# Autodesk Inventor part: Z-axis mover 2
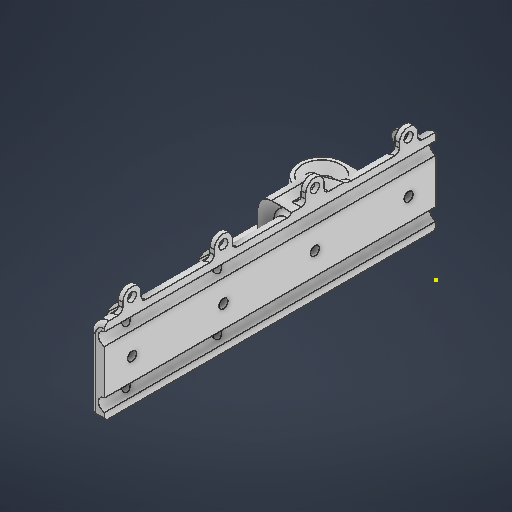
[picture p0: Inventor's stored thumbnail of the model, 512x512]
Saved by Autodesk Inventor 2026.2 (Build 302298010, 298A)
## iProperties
Created: 2026-04
Part Number: Z-axis mover 2
Material: 일반
Document SubType Name: Modeling
Designer: work
Density: 1 g/cm^3
Appearance: 기본값
Author: work
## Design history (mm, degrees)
sketch "스케치1"
  geometry: L1 (0, 0)-(8, 0); L2 (0, 0)-(0, 8); L3 (0, 0)-(-8, 0); L4 (0, 0)-(0, -8); L5 (0, 0)-(50, 0); L6 (0, 0)-(-50, 0); L7 (0, 0)-(0, 50); L8 (25, 0)-(25, -380); L9 (-25, 0)-(-25, -380); L10 (-25, 0)-(-25, 70); L11 (25, -380)-(-25, -380); L12 (25, 0)-(25, 0); L13 (25, 0)-(25, 120); L14 (-37.5, -395)-(37.5, -395); L15 (37.5, -395)-(37.5, -365); L16 (37.5, -365)-(-37.5, -365); L17 (-37.5, -365)-(-37.5, -395); L18 (-37.5, -395)-(37.5, -365); L19 (37.5, -395)-(-37.5, -365); L20 (-62.5, 38)-(62.5, 38); L21 (62.5, 38)-(62.5, -38); L22 (62.5, -38)-(-62.5, -38); L23 (-62.5, -38)-(-62.5, 38); L24 (-62.5, 38)-(62.5, -38); L25 (62.5, 38)-(-62.5, -38); L26 (62.5, -25)-(-62.5, -25); L27 (17, 38)-(-17, 38); L28 (-17, 38)-(-17, 61); L29 (-17, 61)-(17, 61); L30 (17, 61)-(17, 38); L31 (-22, 60.236)-(-22, 100); L32 (-22, 100)-(-28, 100); L33 (-28, 100)-(-28, -380); L34 (-28, -380)-(-22, -380); L35 (-22, -380)-(-22, 100); L36 (-40, 38)-(40, 38); L37 (40, 38)-(40, 18); L38 (40, 18)-(-40, 18); L39 (-40, 18)-(-40, 38); C1 r 5.25 at (0, 0); C2 r 11.3 at (0, 0); C3 r 2 at (8, 0); C4 r 2 at (0, 8); C5 r 2 at (-8, 0); C6 r 2 at (0, -8); C7 r 4.4 at (50, 0); C8 r 4.4 at (-50, 0); C9 r 4 at (0, 50); 7 further points
  constraints: 78 end point, 12 midpoint, 10 parallel, 9 centre point, 9 coincident, 8 horizontal, 6 perpendicular, 6 point on line, 5 vertical, 2 symmetric about line, 1 collinear, 22 other
  dimensions: "d0" = 10.5 diameter of C1; "d1" = 22.6 diameter of C2; "d2" = 8 distance of L1.start L1.end; "d3" = 4 diameter of C3; "d6" = 360 deg dimension on C1.centre L1.end (derived); "d8" = 50 distance of L4.start L5.end; "d9" = 8.8 diameter of C7; "d10" = 50 distance of L4.start L7.end; "d11" = 8 diameter of C9; "d12" = 12 distance of point (0, 38) L7.end; "d15" = 450 distance of L9.end L10.end; "d16" = 25 distance from line of point (0, 0) L8; "d17" = 25 distance from line of L10 C1.centre; "d19" = 500 distance of L8.end L13.end; "d20" = 120 vertical distance of point (0, 0) L13.end; "d21" = 75 distance between parallel lines of L17 L15; "d22" = 30 distance of L14.end L15.end; "d23" = 125 distance between parallel lines of L23 L21; "d24" = 25 distance from line of point (0, 0) L26; "d25" = 340 distance between parallel lines of L16 L26 (derived); "d26" = 34 distance of L28.end L29.end; "d27" = 23 distance of L27.end L28.end; "d30" = 6 distance between parallel lines of L33 L35; "d31" = 80 distance of L37.end L38.end; "d32" = 20 distance of L36.end L37.end; "d60" = 30 distance of L10.end point (-25, 100)
  node "스케치 - 원형 패턴1" dims "d6" = 360 deg (derived)
extrude "돌출1" new body sketch "스케치1" distance "d33" = 6; taper "d34" = 0 deg
extrude "돌출2" join sketch "스케치1" distance "d35" = 4; taper "d36" = 0 deg
extrude "돌출3" join sketch "스케치1" distance "d37" = 38; taper "d38" = 0 deg
sketch "스케치2"
  geometry: L1 (102.5, 6)-(22.5, 6) reference; L2 (87.5, 6)-(87.5, 31); L3 (93.5, 6)-(93.5, 31); L4 (81.5, 31)-(81.5, 6); L5 (0, 0)-(125, 0) reference; L6 (62.5, 6)-(37.5, 6); L7 (37.5, 6)-(37.5, 31); L8 (37.5, 31)-(62.5, 31); L9 (62.5, 31)-(62.5, 6); L10 (30.5, 4)-(44.5, 4); L11 (44.5, 4)-(44.5, 18); L12 (44.5, 18)-(30.5, 18); L13 (30.5, 18)-(30.5, 4); L14 (30.5, 4)-(44.5, 18); L15 (44.5, 4)-(30.5, 18); L16 (44.5, -10.5)-(86.5, -10.5); L17 (86.5, -10.5)-(86.5, 32.5); L18 (86.5, 32.5)-(44.5, 32.5); L19 (44.5, 32.5)-(44.5, -10.5); L20 (44.5, -10.5)-(86.5, 32.5); L21 (86.5, -10.5)-(44.5, 32.5); L22 (47.5, 32.5)-(47.5, -10.5); L23 (37.5, 6)-(37.5, 31); L24 (43.5, 6)-(43.5, 31); L25 (31.5, 31)-(31.5, 6); L26 (47, 1.5)-(28, 1.5); L27 (28, 1.5)-(28, 20.5); L28 (28, 20.5)-(47, 20.5); L29 (47, 20.5)-(47, 1.5); L30 (47, 1.5)-(28, 20.5); L31 (28, 1.5)-(47, 20.5); C1 r 2.75 at (87.5, 6); C2 r 2.75 at (87.5, 31); C3 r 4.25 at (37.5, 31); A1 r 6 centre (87.5, 6) between (81.5, 6) and (93.5, 6); A2 r 6 centre (87.5, 31) between (93.5, 31) and (81.5, 31); A3 r 6 centre (37.5, 6) between (31.5, 6) and (43.5, 6); A4 r 6 centre (37.5, 31) between (43.5, 31) and (31.5, 31); 16 further points
  constraints: 62 end point, 11 midpoint, 10 parallel, 10 tangent, 8 point on circle, 7 centre point, 7 perpendicular, 5 point on line, 4 horizontal, 2 coincident
  dimensions: "d39" = 5.5 diameter of C1; "d40" = 25 distance of L2.start L6.start; "d41" = 25 distance of L2.start L2.end; "d42" = 5.5 diameter of C2; "d43" = 25 distance of L7.end L8.end; "d44" = 25 distance of L6.end L7.end; "d45" = 8.5 diameter of C3; "d46" = 14 distance of L11.end L12.end; "d47" = 14 distance of L10.end L11.end; "d48" = 43 distance of L16.end L17.end; "d50" = 20 distance of L7.end point (37.5, 11); "d51" = 39 distance between parallel lines of L17 L22; "d52" = 3 distance between parallel lines of L22 L19; "d59" = 2.5 distance between parallel lines of L28 L12
extrude "돌출4" join sketch "스케치2" distance "d53" = 145; taper "d54" = 0 deg
extrude "돌출5" cut sketch "스케치2" extent not by distance; stored distance "d55" = 10; taper "d56" = 0 deg
sketch "스케치3"
  geometry: L1 (-31.5, 20.5)-(-31.5, 31) reference; L2 (-43.5, 31)-(-43.5, 20.5) reference; L3 (-30.5, 4)-(-44.5, 4) reference; L4 (-44.5, 18)-(-30.5, 18) reference; L5 (-28, 20.5)-(-31.5, 20.5) reference; L6 (-43.5, 20.5)-(-47, 20.5) reference; L7 (-47, 1.5)-(-41.469, 1.5) reference; L8 (-33.531, 1.5)-(-28, 1.5) reference; L9 (-28, 1.5)-(-28, 20.5) reference; L10 (-30.5, 18)-(-30.5, 4) reference; L11 (-44.5, 4)-(-44.5, 18) reference; L12 (-47, 20.5)-(-47, 1.5) reference; C1 r 6 at (-37.5, 31); A1 r 6 centre (-37.5, 6) between (-41.469, 1.5) and (-33.531, 1.5) reference; A2 r 6 centre (-37.5, 31) between (-31.5, 31) and (-43.5, 31) reference; 5 further points
  constraints: 1 centre point, 1 concentric
extrude "돌출6" cut sketch "스케치3" stored distance "d57" = 145; taper "d58" = 0 deg
sketch "스케치5"
  geometry: L1 (29.25, 38)-(20.75, 38) reference; L2 (18, 38)-(32, 38) reference; L3 (32, 38)-(18, 38) reference; L4 (-25, 38)-(62.5, 38) reference; L5 (40, 38)-(62.5, 38) reference; L6 (-40, 38)-(40, 38) reference; L7 (-62.5, 38)-(-40, 38) reference; L8 (-62.5, 38)-(-25, 38) reference; L9 (-25, 38)-(-31, 38) reference; L10 (-31, 38)-(-19, 38) reference; L11 (-19, 38)-(-25, 38) reference; L12 (25, 38)-(25, 88); L13 (9.5, 103.5)-(40.5, 103.5); L14 (40.5, 103.5)-(40.5, 72.5); L15 (40.5, 72.5)-(9.5, 72.5); L16 (9.5, 72.5)-(9.5, 103.5); L17 (9.5, 103.5)-(40.5, 72.5); L18 (40.5, 103.5)-(9.5, 72.5); L19 (1.5, 111.5)-(48.5, 111.5); L20 (48.5, 111.5)-(48.5, 64.5); L21 (48.5, 64.5)-(1.5, 64.5); L22 (1.5, 64.5)-(1.5, 111.5); L23 (1.5, 111.5)-(48.5, 64.5); L24 (48.5, 111.5)-(1.5, 64.5); L25 (-22.25, 120)-(-22.25, -25) reference; L26 (-31, 38)-(-19, 38) reference; L27 (-31, 38)-(-31, 120) reference; L28 (-19, 120)-(-31, 120) reference; L29 (-19, 38)-(-19, 120) reference; L30 (62.5, 38)-(62.5, -25) reference; L31 (40, 18)-(40, 38) reference; L32 (-62.5, 38)-(-25, 38) reference; L33 (-62.5, -25)-(-62.5, 38) reference; L34 (62.5, -25)-(-62.5, -25) reference; L35 (62.5, 38)-(62.5, -25) reference; L36 (-25, 38)-(62.5, 38) reference; L37 (-19, 38)-(19, 38); L38 (19, 38)-(19, 62); L39 (19, 62)-(-19, 62); L40 (-19, 62)-(-19, 38); L41 (-19, 38)-(-19, 120) reference; C1 r 12.5 at (25, 88); C2 r 2 at (9.5, 72.5); C3 r 2 at (40.5, 103.5); C4 r 2 at (9.5, 103.5); C5 r 2 at (40.5, 72.5); C6 r 2 at (0, -8) reference; C7 r 2 at (8, 0) reference; C8 r 2 at (0, 8) reference; C9 r 2 at (-8, 0) reference; C10 r 5.25 at (0, 0) reference; C11 r 4.4 at (50, 0) reference; C12 r 4.4 at (-50, 0) reference; A1 r 28.971 centre (1.5, 140.471) between (-19, 120) and (1.5, 111.5); A2 r 15 centre (63.5, 64.5) between (48.5, 64.5) and (55.046, 52.109); A3 r 17.08 centre (45.42, 38) between (62.5, 38) and (55.046, 52.109); 15 further points
  constraints: 34 end point, 8 centre point, 6 parallel, 6 point on circle, 5 coincident, 5 midpoint, 4 perpendicular, 4 tangent, 3 horizontal, 2 point on line, 5 other
  dimensions: "d61" = 25 distance from line of point (0, 38) L12; "d62" = 25 diameter of C1; "d63" = 31 distance of L14.end L15.end; "d64" = 31 distance of L13.end L14.end; "d65" = 4 diameter of C2; "d66" = 4 diameter of C3; "d67" = 4 diameter of C4; "d68" = 4 diameter of C5; "d69" = 50 distance of L12.start L12.end; "d70" = 8 distance between parallel lines of L14 L20; "d71" = 15 radius of A2; "d73" = 24 distance of L39.end L37.start
extrude "돌출7" join sketch "스케치5" distance "d74" = 6; taper "d75" = 0 deg
sketch "스케치6"
  geometry: L1 (-81.5, 31)-(-81.5, 0) reference; L2 (-81.5, 0)-(-43.5, 0) reference; L3 (-43.5, 0)-(-43.5, 4) reference; L4 (-30.5, 6)-(-22.5, 6) reference; L5 (-44.5, 18)-(-44.5, 4) reference; L6 (-30.5, 18)-(-44.5, 18) reference; L7 (-30.5, 6)-(-30.5, 18) reference; L8 (-22.5, 6)-(-22.5, 38) reference; L9 (-102.5, 38)-(-22.5, 38) reference; L10 (-102.5, 6)-(-102.5, 38) reference; L11 (-125, 6)-(-102.5, 6) reference; L12 (-125, 0)-(-125, 6) reference; L13 (-125, 0)-(-93.5, 0) reference; L14 (-93.5, 0)-(-93.5, 31) reference; L15 (-81.5, 6)-(-81.5, 31) reference; L16 (-93.5, 31)-(-93.5, 0) reference; L17 (0, 0)-(-125, 0) reference; L18 (-93.5, 6)-(-81.5, 6); L19 (-81.5, 6)-(-81.5, 0); L20 (-81.5, 0)-(-93.5, 0); L21 (-93.5, 0)-(-93.5, 6); L22 (-81.5, 0)-(-93.5, 0) reference; L23 (-81.5, 0)-(-81.5, 6) reference; L24 (-90.25, 6)-(-84.75, 6) reference; L25 (-44.5, 4)-(-43.5, 4) reference; C1 r 4.25 at (-37.5, 31) reference; C2 r 2.75 at (-87.5, 31) reference; A1 r 6 centre (-87.5, 31) between (-81.5, 31) and (-93.5, 31) reference; A2 r 6 centre (-87.5, 31) between (-81.5, 31) and (-93.5, 31) reference; A3 r 2.75 centre (-87.5, 6) between (-84.75, 6) and (-90.25, 6) reference; 10 further points
  constraints: 8 end point, 2 parallel, 2 point on line, 1 horizontal, 1 perpendicular
extrude "돌출8" join sketch "스케치6" stored distance "d76" = 6; taper "d77" = 0 deg
sketch "스케치7"
  geometry: L1 (47, 6)-(81.5, 6) reference; L2 (47, 20.5)-(43.5, 20.5) reference; L3 (43.5, 20.5)-(43.5, 31) reference; L4 (31.5, 31)-(31.5, 20.5) reference; L5 (31.5, 20.5)-(28, 20.5) reference; L6 (28, 20.5)-(28, 6) reference; L7 (0, 6)-(28, 6) reference; L8 (0, 0)-(0, 6) reference; L9 (0, 0)-(125, 0) reference; L10 (125, 0)-(125, 6) reference; L11 (93.5, 6)-(125, 6) reference; L12 (93.5, 6)-(93.5, 31) reference; L13 (81.5, 31)-(81.5, 6) reference; L14 (44.5, 18)-(44.5, 4) reference; L15 (44.5, 4)-(30.5, 4) reference; L16 (30.5, 4)-(30.5, 18) reference; L17 (30.5, 18)-(44.5, 18) reference; L18 (43.5, 4)-(30.5, 4) reference; L19 (43.5, 4)-(43.5, 6) reference; L20 (30.5, 6)-(43.5, 6) reference; L21 (30.5, 4)-(30.5, 6) reference; L22 (81.5, 0)-(43.5, 0) reference; L23 (81.5, 0)-(81.5, 6) reference; L24 (43.5, 6)-(81.5, 6) reference; L25 (43.5, 0)-(43.5, 6) reference; L26 (47, 6)-(47, 20.5) reference; C1 r 2.75 at (87.5, 31) reference; C2 r 2.75 at (87.5, 6) reference; C3 r 2.75 at (87.5, 31) reference; A1 r 6 centre (37.5, 31) between (43.5, 31) and (31.5, 31) reference; A2 r 6 centre (87.5, 31) between (93.5, 31) and (81.5, 31) reference; 4 further points
extrude "돌출9" cut sketch "스케치7" extent not by distance; stored distance "d78" = 0; taper "d79" = 0 deg
sketch "스케치8"
  geometry: L1 (50.5, 10)-(74.5, 10); L2 (74.5, 10)-(74.5, 28); L3 (74.5, 28)-(50.5, 28); L4 (50.5, 28)-(50.5, 10); L5 (50.5, 10)-(74.5, 28); L6 (74.5, 10)-(50.5, 28); L7 (102.5, 38)-(22.5, 38) reference; L8 (62.5, 38)-(62.5, 0); C1 r 2 at (50.5, 28); C2 r 2 at (50.5, 10); C3 r 2 at (74.5, 10); C4 r 2 at (74.5, 28); 1 further point
  constraints: 14 end point, 4 centre point, 4 coincident, 4 midpoint, 2 parallel, 1 horizontal, 1 perpendicular, 1 vertical
  dimensions: "d80" = 24 distance of L3.end L2.end; "d81" = 18 distance of L2.end L1.end; "d82" = 4 diameter of C1; "d83" = 4 diameter of C2; "d84" = 4 diameter of C3; "d85" = 4 diameter of C4
extrude "돌출10" cut sketch "스케치8" extent not by distance; stored distance "d86" = 18 (derived); taper "d87" = 0 deg
sketch "스케치9"
  geometry: L1 (59, -32)-(59, -7) reference; L2 (71, -7)-(71, -32) reference; L3 (80, -32)-(71, -32) reference; L4 (80, -32)-(80, 0) reference; L5 (0, 0)-(80, 0) reference; L6 (0, -32)-(0, 0) reference; L7 (5.5, -32)-(0, -32) reference; L8 (5.5, -32)-(5.5, -17.5) reference; L9 (5.5, -17.5)-(9, -17.5) reference; L10 (9, -17.5)-(9, -7) reference; L11 (21, -7)-(21, -17.5) reference; L12 (21, -17.5)-(24.5, -17.5) reference; L13 (59, -32)-(24.5, -32) reference; L14 (24.5, -17.5)-(24.5, -32) reference; C1 r 2 at (28, -28) reference; C2 r 2 at (52, -28) reference; C3 r 2 at (28, -10) reference; C4 r 2 at (52, -10) reference; C5 r 2 at (52, -28) reference; A1 r 6 centre (65, -7) between (71, -7) and (59, -7) reference; A2 r 6 centre (15, -7) between (21, -7) and (9, -7) reference; 5 further points
  constraints: 4 coincident
hole "구멍1" sketch "스케치9" at (52, -10), (28, -10), (28, -28), (52, -28) diameter "d88" = 4; stored, may be unused: countersink angle "d92" = 90 deg, drill point angle "d94" = 0 deg; dims "d89" = 6, "d90" = 6.2, "d91" = 4, "d93" = 8
sketch "스케치10"
  geometry: L1 (32, -98.356)-(32, -111.5) reference; L2 (32, -111.5)-(48.5, -111.5) reference; L3 (48.5, -111.5)-(48.5, -64.5) reference; L4 (62.5, -38)-(62.5, 25) reference; L5 (62.5, 25)-(34.5, 25) reference; L6 (34.5, 25)-(34.5, -18) reference; L7 (34.5, -18)-(40, -18) reference; L8 (40, -18)-(40, -38) reference; L9 (32, -38)-(40, -38) reference; L10 (32, -38)-(32, -77.644) reference; L11 (-31, -18)-(-31, 25) reference; L12 (-31, 25)-(-62.5, 25) reference; L13 (-62.5, 25)-(-62.5, -38) reference; L14 (-62.5, -38)-(-40, -38) reference; L15 (-40, -38)-(-40, -18) reference; L16 (-40, -18)-(-31, -18) reference; L17 (-50, -10)-(-31, -10); L18 (-50, 10)-(-31, 10); L19 (50, 10)-(34.5, 10); L20 (50, -10)-(34.5, -10); C1 r 4.4 at (50, 0) reference; C2 r 2 at (40.5, -72.5) reference; C3 r 2 at (40.5, -103.5) reference; C4 r 4.4 at (-50, 0) reference; A1 r 15 centre (63.5, -64.5) between (55.046, -52.109) and (48.5, -64.5) reference; A2 r 17.08 centre (45.42, -38) between (55.046, -52.109) and (62.5, -38) reference; A3 r 12.5 centre (25, -88) between (32, -98.356) and (32, -77.644) reference; A4 r 10 centre (-50, 0) between (-50, -10) and (-50, 10); A5 r 10 centre (50, 0) between (50, 10) and (50, -10); 1 further point
  constraints: 8 end point, 4 perpendicular, 4 point on circle, 4 point on line, 4 tangent, 2 centre point, 2 coincident
  dimensions: "d95" = 20 diameter of A4; "d96" = 20 diameter of A5
extrude "돌출11" join sketch "스케치10" stored distance "d97" = 10; taper "d98" = 0 deg
fillet "모깎기1" dims "d99" = 6
sketch "스케치11"
  geometry: C1 r 4.25 at (0, 0) reference; 1 further point
extrude "돌출12" cut sketch "스케치11" extent not by distance; stored distance "d100" = 0; taper "d101" = 0 deg
fillet "모깎기2" dims "d102" = 2
fillet "모깎기3" dims "d103" = 0.5
chamfer "모따기1" distance "d104" = 1; stored, may be unused: second distance "d105" = 2, angle "d106" = 45 deg
sketch "스케치12"
  geometry: L1 (17.5, -61.936)-(17.5, -78) reference; L2 (17, -62)-(-17, -62) reference; L3 (-19, -60)-(-19, -118) reference; L4 (-21, -120)-(-19.813, -120) reference; L5 (1.5, -111.5)-(17.5, -111.5) reference; L6 (17.5, -98)-(17.5, -111.5) reference; L7 (42, -40)-(42, -17.621) reference; L8 (32.5, -78)-(32.5, -40) reference; L9 (32.5, -111.5)-(32.5, -98) reference; L10 (32.5, -111.5)-(42.5, -111.5) reference; L11 (48.5, -105.5)-(48.5, -64.5) reference; L12 (62.5, -38)-(62.5, 19) reference; L13 (56.5, 25)-(36.5, 25) reference; L14 (36.5, 16)-(36.5, 25) reference; L15 (50, 12)-(40.5, 12) reference; L16 (45.657, -12)-(50, -12) reference; L17 (42, -40)-(42, -17.621) reference; L18 (32.5, -40)-(42, -40) reference; C1 r 2 at (9.5, -72.5) reference; C2 r 2 at (9.5, -103.5) reference; C3 r 2 at (40.5, -103.5) reference; C4 r 2 at (40.5, -72.5) reference; C5 r 2 at (40.5, -103.5) reference; A1 r 2 centre (17, -60) between (17, -62) and (17.5, -61.936) reference; A2 r 2 centre (-17, -60) between (-19, -60) and (-17, -62) reference; A3 r 2 centre (-21, -118) between (-21, -120) and (-19, -118) reference; A4 r 2 centre (-19.813, -118) between (-19.813, -120) and (-18.437, -119.451) reference; A5 r 28.971 centre (1.5, -140.471) between (1.5, -111.5) and (-18.437, -119.451) reference; A6 r 12.5 centre (25, -88) between (17.5, -78) and (17.5, -98) reference; A7 r 12.5 centre (25, -88) between (32.5, -98) and (32.5, -78) reference; A8 r 6 centre (42.5, -105.5) between (42.5, -111.5) and (48.5, -105.5) reference; A9 r 15 centre (63.5, -64.5) between (55.046, -52.109) and (48.5, -64.5) reference; A10 r 17.08 centre (45.42, -38) between (55.046, -52.109) and (62.5, -38) reference; A11 r 6 centre (56.5, 19) between (62.5, 19) and (56.5, 25) reference; A12 r 4 centre (40.5, 16) between (36.5, 16) and (40.5, 12) reference; A13 r 12 centre (50, 0) between (50, -12) and (50, 12) reference; A14 r 4 centre (45.657, -16) between (45.657, -12) and (42, -17.621) reference; 5 further points
  constraints: 4 coincident
hole "구멍2" sketch "스케치12" at (9.5, -103.5), (40.5, -103.5), (40.5, -72.5), (9.5, -72.5) diameter "d107" = 4; stored, may be unused: countersink angle "d111" = 90 deg, drill point angle "d113" = 0 deg; dims "d108" = 6, "d109" = 6.2, "d110" = 4, "d112" = 8
fillet "모깎기4" dims "d114" = 10
sketch "스케치13"
  geometry: L1 (78, -30)-(0, -30) reference; L2 (78, 0)-(78, -30) reference; L3 (0, 0)-(78, 0) reference; L4 (0, -30)-(0, 0) reference; L5 (68, 0)-(28, 0); L6 (28, 0)-(28, -25); L7 (28, -25)-(68, -25); L8 (68, -25)-(68, 0); C1 r 4 at (28, 0); C2 r 4 at (28, -25); C3 r 4 at (68, -25); C4 r 4 at (68, 0); 1 further point
  constraints: 8 end point, 4 centre point, 2 parallel, 1 coincident, 1 horizontal, 1 perpendicular, 1 point on line
  dimensions: "d115" = 40 distance of L7.end L6.end; "d116" = 25 distance of L6.end L5.end; "d117" = 10 distance between parallel lines of L2 L8; "d118" = 8 diameter of C1; "d119" = 8 diameter of C2; "d120" = 8 diameter of C3; "d121" = 8 diameter of C4
  node "투영된 루프17"
extrude "돌출13" join sketch "스케치13" stored distance "d122" = 8 (derived); taper "d123" = 0 deg
extrude "돌출14" join sketch "스케치13" distance "d124" = 1.5; taper "d125" = 0 deg
sketch "스케치14"
  geometry: L1 (4, 0)-(36, 0) reference; L2 (-28, 0)-(-4, 0) reference; L3 (-28, -30)-(-28, 0) reference; L4 (50, -30)-(-28, -30) reference; L5 (50, 0)-(50, -30) reference; L6 (44, 0)-(50, 0) reference; C1 r 4 at (40, -25) reference; C2 r 4 at (0, -25) reference; C3 r 2 at (0, 0); C4 r 2 at (0, -25); C5 r 2 at (40, -25); C6 r 2 at (40, 0); A1 r 4 centre (40, 0) between (36, 0) and (44, 0) reference; A2 r 4 centre (0, 0) between (-4, 0) and (4, 0) reference; 1 further point
  constraints: 4 centre point, 4 coincident
  dimensions: "d126" = 4 diameter of C3; "d127" = 4 diameter of C4; "d128" = 4 diameter of C5; "d129" = 4 diameter of C6
  node "투영된 루프18"
extrude "돌출15" cut sketch "스케치14" stored distance "d130" = 1.5; taper "d131" = 0 deg; dims "d0" = 10.5, "d1" = 22.6, "d2" = 8, "d3" = 4, "d6" = 360 deg (derived), "d8" = 50, "d9" = 8.8, "d10" = 50, "d11" = 8, "d12" = 12, "d15" = 450, "d16" = 25, "d17" = 25, "d19" = 500, "d20" = 120, "d21" = 75, "d22" = 30, "d23" = 125, "d24" = 25, "d25" = 340 (derived), "d26" = 34, "d27" = 23, "d30" = 6, "d31" = 80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
extrude "돌출16" cut sketch "스케치14" stored distance "d132" = 10; taper "d133" = 0 deg; dims "d0" = 10.5, "d1" = 22.6, "d2" = 8, "d3" = 4, "d6" = 360 deg (derived), "d8" = 50, "d9" = 8.8, "d10" = 50, "d11" = 8, "d12" = 12, "d15" = 450, "d16" = 25, "d17" = 25, "d19" = 500, "d20" = 120, "d21" = 75, "d22" = 30, "d23" = 125, "d24" = 25, "d25" = 340 (derived), "d26" = 34, "d27" = 23, "d30" = 6, "d31" = 80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
fillet "모깎기5" dims "d134" = 2
sketch "스케치15"
  geometry: L1 (-21.127, -38)-(34, -38) reference; L2 (25, -38)-(25, -18); C1 r 2 at (25, -18); C2 r 2 at (25, -30); 1 further point
  constraints: 2 centre point, 2 end point, 2 point on line, 1 coincident, 1 vertical
  dimensions: "d135" = 20 distance of L2.start L2.end; "d136" = 25 distance from line of L2 point (0, 0); "d137" = 4 diameter of C1; "d138" = 4 diameter of C2; "d139" = 12 distance of L2.end C2.centre
extrude "돌출17" cut sketch "스케치15" stored distance "d140" = 10; taper "d141" = 0 deg
sketch "스케치16" dims "d145" = 7
  geometry: L1 (13, -21.5)-(13, -1.9); L2 (8, -25)-(31.5, -25) reference; L3 (6, -23)-(6, 0) reference; L4 (13, -5.4)-(6, -5.4); L5 (13, 1.6)-(5.783, 1.6); L6 (13, -18)-(6, -18); L7 (-42.5, -26.5)-(-42.5, -13.5) reference; L8 (-56.5, -27.5)-(-43.5, -27.5) reference; L9 (-57.5, -13.5)-(-57.5, -26.5) reference; L10 (-43.5, -12.5)-(-56.5, -12.5) reference; L11 (31.5, -30)-(-81.5, -30) reference; L12 (31.5, -25)-(31.5, -30) reference; L13 (8, -25)-(31.5, -25) reference; L14 (6, -23)-(6, 0) reference; L15 (-6, 0)-(-6, -23) reference; L16 (-38.5, -25)-(-8, -25) reference; L17 (-40.5, -23)-(-40.5, -12.5) reference; L18 (-42.5, -10.5)-(-44, -10.5) reference; L19 (-44, -10.5)-(-44, 0) reference; L20 (-56, 0)-(-56, -10.5) reference; L21 (-56, -10.5)-(-57.5, -10.5) reference; L22 (-59.5, -12.5)-(-59.5, -23) reference; L23 (-81.5, -25)-(-61.5, -25) reference; L24 (-81.5, -30)-(-81.5, -25) reference; C1 r 2 at (13, -21.5); C2 r 2 at (13, -1.9); C3 r 4.25 at (-50, 0) reference; C4 r 2.75 at (0, 0) reference; C5 r 2.75 at (0, -25) reference; A1 r 3.5 centre (13, -1.9) between (13, -5.4) and (13, 1.6); A2 r 6 centre (0, 0) between (6, 0) and (-6, 0) reference; A3 r 1 centre (-43.5, -13.5) between (-42.5, -13.5) and (-43.5, -12.5) reference; A4 r 1 centre (-43.5, -26.5) between (-43.5, -27.5) and (-42.5, -26.5) reference; A5 r 1 centre (-56.5, -26.5) between (-57.5, -26.5) and (-56.5, -27.5) reference; A6 r 1 centre (-56.5, -13.5) between (-56.5, -12.5) and (-57.5, -13.5) reference; A7 r 2 centre (8, -23) between (6, -23) and (8, -25) reference; A8 r 6 centre (0, 0) between (6, 0) and (-6, 0) reference; A9 r 2 centre (-8, -23) between (-8, -25) and (-6, -23) reference; A10 r 2 centre (-38.5, -23) between (-40.5, -23) and (-38.5, -25) reference; A11 r 2 centre (-42.5, -12.5) between (-40.5, -12.5) and (-42.5, -10.5) reference; A12 r 6 centre (-50, 0) between (-44, 0) and (-56, 0) reference; A13 r 2 centre (-57.5, -12.5) between (-57.5, -10.5) and (-59.5, -12.5) reference; A14 r 2 centre (-61.5, -23) between (-61.5, -25) and (-59.5, -23) reference; 5 further points
  constraints: 8 end point, 4 point on line, 3 centre point, 3 coincident, 3 perpendicular, 3 point on circle, 2 horizontal, 1 tangent, 1 vertical, 3 other
  dimensions: "d142" = 4 diameter of C1; "d143" = 4 diameter of C2; "d144" = 7 diameter of A1; "d146" = 19.6 distance of L1.start L1.end; "d147" = 7 distance from line of L3 L1.start
extrude "돌출18" join sketch "스케치16" distance "d148" = 3; taper "d149" = 0 deg
fillet "모깎기6" dims "d150" = 1
sketch "스케치17"
  geometry: L1 (0, 0)-(0, 25); L2 (13.5, 25)-(-17, 25) reference; L3 (7.5, 21)-(-7.5, 21); L4 (58.5, -34)-(58.5, -19); L5 (62.5, -38)-(62.5, 19) reference; C1 r 2 at (-7.5, 21); C2 r 2 at (7.5, 21); C3 r 2 at (58.5, -34); C4 r 2 at (58.5, -19); 1 further point
  constraints: 6 end point, 4 centre point, 4 coincident, 2 point on line, 2 vertical, 1 horizontal, 1 midpoint
  dimensions: "d151" = 15 distance of L3.start L3.end; "d152" = 4 diameter of C1; "d153" = 4 diameter of C2; "d154" = 4 distance between parallel lines of L2 L3; "d155" = 15 distance of L4.start L4.end; "d156" = 4 diameter of C3; "d157" = 4 diameter of C4; "d158" = 4 distance between parallel lines of L5 L4; "d159" = 4 horizontal distance of L5.start L4.start
extrude "돌출19" cut sketch "스케치17" extent not by distance; stored distance "d160" = 0; taper "d161" = 0 deg
sketch "스케치18"
  geometry: L1 (-42, -17.621)-(-42, -38) reference; L2 (-50, -12)-(-45.657, -12) reference; C1 r 16 at (-60, -30); 1 further point
  constraints: 1 centre point
  dimensions: "d162" = 32 diameter of C1; "d163" = 2 distance edge to line of C1 L1; "d164" = 2 distance edge to line of C1 L2
extrude "돌출20" cut sketch "스케치18" distance "d165" = 2; taper "d166" = 0 deg
sketch "스케치19"
  geometry: L1 (56.5, 19)-(42.5, 19); L2 (56.5, 23)-(42.5, 23); L3 (42.5, 15)-(56.5, 15); L4 (36.5, 16)-(36.5, 25) reference; L5 (-56.5, 19)-(-48, 19); L6 (-56.5, 15)-(-48, 15); L7 (-48, 23)-(-56.5, 23); L8 (-46.144, -38)-(-42, -38) reference; L9 (-42, -17.621)-(-42, -38) reference; L10 (-50, -12)-(-45.657, -12) reference; L11 (-37, 12)-(-50, 12) reference; L12 (-33, 21)-(-33, 16) reference; L13 (-41.742, 21)-(-33, 21) reference; L14 (-41.742, 25)-(-56.5, 25) reference; L15 (-62.5, 19)-(-62.5, -14.197) reference; L16 (36.5, -52)-(44.5, -52); L17 (44.5, -52)-(44.5, -44); L18 (44.5, -44)-(36.5, -44); L19 (36.5, -44)-(36.5, -52); L20 (32.5, -40)-(42, -40) reference; L21 (32.5, -78)-(32.5, -40) reference; L22 (13.5, 25)-(13.5, -16.011) reference; L23 (13.5, 25)-(-17, 25) reference; L24 (-17, -12)-(-17, 25) reference; L25 (9.631, -16)-(-9.631, -16) reference; L26 (32.5, -78)-(32.5, -40) reference; L27 (32.5, -111.5)-(32.5, -98) reference; L28 (32.5, -111.5)-(42.5, -111.5) reference; L29 (48.5, -105.5)-(48.5, -64.5) reference; L30 (62.5, -38)-(62.5, 19) reference; L31 (56.5, 25)-(36.5, 25) reference; L32 (36.5, 16)-(36.5, 25) reference; L33 (50, 12)-(40.5, 12) reference; L34 (45.657, -12)-(50, -12) reference; L35 (42, -40)-(42, -17.621) reference; L36 (32.5, -40)-(42, -40) reference; L37 (-41.742, 25)-(-41.742, 21) reference; C1 r 1.5 at (36.5, -52); C2 r 1.5 at (36.5, -44); C3 r 1.5 at (44.5, -44); C4 r 1.5 at (44.5, -52); A1 r 4 centre (56.5, 19) between (56.5, 15) and (56.5, 23); A2 r 4 centre (42.5, 19) between (42.5, 23) and (42.5, 15); A3 r 6 centre (56.5, 19) between (62.5, 19) and (56.5, 25) reference; A4 r 4 centre (-56.5, 19) between (-56.5, 23) and (-56.5, 15); A5 r 4 centre (-48, 19) between (-48, 15) and (-48, 23); A6 r 6 centre (-56.5, 19) between (-56.5, 25) and (-62.5, 19) reference; A7 r 16 centre (-60, -30) between (-46.144, -38) and (-62.5, -14.197) reference; A8 r 4 centre (-45.657, -16) between (-42, -17.621) and (-45.657, -12) reference; A9 r 12 centre (-50, 0) between (-50, 12) and (-50, -12) reference; A10 r 4 centre (-37, 16) between (-37, 12) and (-33, 16) reference; A11 r 6 centre (-56.5, 19) between (-56.5, 25) and (-62.5, 19) reference; A12 r 4 centre (-13, -12) between (-17, -12) and (-13.912, -15.895) reference; A13 r 12.5 centre (25, -88) between (32.5, -98) and (32.5, -78) reference; A14 r 6 centre (42.5, -105.5) between (42.5, -111.5) and (48.5, -105.5) reference; A15 r 15 centre (63.5, -64.5) between (55.046, -52.109) and (48.5, -64.5) reference; A16 r 17.08 centre (45.42, -38) between (55.046, -52.109) and (62.5, -38) reference; A17 r 6 centre (56.5, 19) between (62.5, 19) and (56.5, 25) reference; A18 r 4 centre (40.5, 16) between (36.5, 16) and (40.5, 12) reference; A19 r 12 centre (50, 0) between (50, -12) and (50, 12) reference; A20 r 4 centre (45.657, -16) between (45.657, -12) and (42, -17.621) reference; 8 further points
  constraints: 24 end point, 10 point on circle, 8 centre point, 8 tangent, 4 coincident, 4 parallel, 3 horizontal, 3 midpoint, 2 concentric, 1 perpendicular, 4 other
  dimensions: "d167" = 8 diameter of A2; "d168" = 2 distance from line of point (38.5, 19) L4; "d169" = 8 diameter of A5; "d171" = 3 diameter of C1; "d172" = 3 diameter of C2; "d173" = 3 diameter of C3; "d174" = 3 diameter of C4; "d175" = 8 distance of L16.end L17.end; "d176" = 8 distance of L17.end L18.end; "d177" = 4 distance between parallel lines of L20 L18; "d178" = 4 distance from line of L21 point (36.5, -48)
extrude "돌출21" cut sketch "스케치19" extent not by distance; stored distance "d179" = 0; taper "d180" = 0 deg
sketch "스케치20"
  geometry: 1 further point
sketch "스케치21"
  geometry: L1 (7.5, -26.5)-(7.5, -13.5) reference; L2 (-6.5, -27.5)-(6.5, -27.5) reference; L3 (-7.5, -13.5)-(-7.5, -26.5) reference; L4 (6.5, -12.5)-(-6.5, -12.5) reference; L5 (81.5, -30)-(-31.5, -30) reference; L6 (81.5, -25)-(81.5, -30) reference; L7 (66.742, -25)-(81.5, -25) reference; L8 (63, -18)-(57, -18) reference; L9 (56, -17)-(56, -6.4) reference; L10 (57, -5.4)-(63, -5.4) reference; L11 (63, 1.6)-(56.499, 1.6) reference; L12 (44, 0)-(44, -23) reference; L13 (11.5, -25)-(42, -25) reference; L14 (9.5, -23)-(9.5, -12.5) reference; L15 (7.5, -10.5)-(6, -10.5) reference; L16 (6, -10.5)-(6, 0) reference; L17 (-6, 0)-(-6, -10.5) reference; L18 (-6, -10.5)-(-7.5, -10.5) reference; L19 (-9.5, -12.5)-(-9.5, -23) reference; L20 (-31.5, -25)-(-11.5, -25) reference; L21 (-31.5, -30)-(-31.5, -25) reference; L22 (-9.5, -12.5)-(-9.5, -7.5); L23 (-7.5, -5.5)-(7.5, -5.5); L24 (9.5, -12.5)-(9.5, -7.5); L25 (7.5, -13.5)-(7.5, -7.5); L26 (7.5, -7.5)-(-7.5, -7.5); L27 (-7.5, -7.5)-(-7.5, -13.5); L28 (-9.5, -13.5)-(9.5, -13.5); C1 r 2 at (63, -1.9) reference; C2 r 2 at (63, -21.5) reference; C3 r 4.25 at (0, 0) reference; C4 r 2.75 at (50, 0) reference; C5 r 2.75 at (50, -25) reference; A1 r 1 centre (6.5, -13.5) between (7.5, -13.5) and (6.5, -12.5) reference; A2 r 1 centre (6.5, -26.5) between (6.5, -27.5) and (7.5, -26.5) reference; A3 r 1 centre (-6.5, -26.5) between (-7.5, -26.5) and (-6.5, -27.5) reference; A4 r 1 centre (-6.5, -13.5) between (-6.5, -12.5) and (-7.5, -13.5) reference; A5 r 1 centre (66.742, -24) between (65.91, -23.444) and (66.742, -25) reference; A6 r 3.5 centre (63, -21.5) between (65.91, -23.444) and (63, -18) reference; A7 r 1 centre (57, -17) between (56, -17) and (57, -18) reference; A8 r 1 centre (57, -6.4) between (57, -5.4) and (56, -6.4) reference; A9 r 3.5 centre (63, -1.9) between (63, -5.4) and (63, 1.6) reference; A10 r 1 centre (56.499, 2.6) between (55.571, 2.229) and (56.499, 1.6) reference; A11 r 6 centre (50, 0) between (55.571, 2.229) and (44, 0) reference; A12 r 2 centre (42, -23) between (42, -25) and (44, -23) reference; A13 r 2 centre (11.5, -23) between (9.5, -23) and (11.5, -25) reference; A14 r 2 centre (7.5, -12.5) between (9.5, -12.5) and (7.5, -10.5) reference; A15 r 6 centre (0, 0) between (6, 0) and (-6, 0) reference; A16 r 2 centre (-7.5, -12.5) between (-7.5, -10.5) and (-9.5, -12.5) reference; A17 r 2 centre (-11.5, -23) between (-11.5, -25) and (-9.5, -23) reference; A18 r 2 centre (-7.5, -7.5) between (-7.5, -5.5) and (-9.5, -7.5); A19 r 2 centre (7.5, -7.5) between (9.5, -7.5) and (7.5, -5.5); A20 r 2 centre (-5.5, -9.5) between (-5.5, -7.5) and (-7.5, -9.5); A21 r 2 centre (5.5, -9.5) between (7.5, -9.5) and (5.5, -7.5); 8 further points
  constraints: 14 end point, 8 point on circle, 8 tangent, 6 point on line, 4 centre point, 2 vertical, 1 horizontal, 1 midpoint, 1 perpendicular, 12 other
  dimensions: "d181" = 7 distance from line of L4 point (0, -5.5); "d182" = 2 radius of A19; "d183" = 2 radius of A18; "d184" = 2 radius of A20; "d185" = 2 radius of A21; "d186" = 1 distance between parallel lines of L4 L28
  node "투영된 루프21"
extrude "돌출22" join sketch "스케치21" stored distance "d187" = 10; taper "d188" = 0 deg
extrude "돌출23" cut sketch "스케치21" extent not by distance; stored distance "d189" = 10; taper "d190" = 0 deg
chamfer "모따기2" distance "d191" = 0.5; stored, may be unused: second distance "d192" = 2, angle "d193" = 45 deg
node "작업 평면1"
sketch "스케치22"
  geometry: L1 (-37, 16.5)-(0, 16.5) reference; L2 (5.97, 17.5)-(26, 17.5) reference; L3 (28, 16.5)-(106, 16.5) reference; L4 (96, 12.5)-(96, 20.5); L5 (100, 12.5)-(100, 20.5); L6 (92, 20.5)-(92, 12.5); L7 (108, 13.25)-(108, 7.75) reference; L8 (52, 20.5)-(52, 12.5); L9 (60, 12.5)-(60, 20.5); L10 (56, 12.5)-(56, 20.5); L11 (11.985, 21.8)-(11.985, 14.348); L12 (19.985, 11.991)-(19.985, 21.8); L13 (15.985, 13.2)-(15.985, 21.8); L14 (-29, 20.5)-(-29, 12.5); L15 (-21, 12.5)-(-21, 20.5); L16 (-25, 12.5)-(-25, 20.5); L17 (-29, 14.5)-(-21, 14.5); L18 (11.985, 15.5)-(19.985, 15.5); L19 (52, 14.5)-(60, 14.5); L20 (92, 14.5)-(100, 14.5); C1 r 2 at (96, 20.5); C2 r 2 at (56, 20.5); C3 r 2 at (15.985, 21.8); C4 r 2 at (-25, 20.5); A1 r 4 centre (96, 12.5) between (92, 12.5) and (100, 12.5); A2 r 4 centre (96, 20.5) between (100, 20.5) and (92, 20.5); A3 r 4 centre (56, 20.5) between (60, 20.5) and (52, 20.5); A4 r 4 centre (15.985, 21.8) between (19.985, 21.8) and (11.985, 21.8); A5 r 4 centre (-25, 20.5) between (-21, 20.5) and (-29, 20.5); 7 further points
  constraints: 40 end point, 15 point on line, 10 point on circle, 10 tangent, 9 centre point, 7 perpendicular, 5 midpoint, 4 coincident, 4 parallel, 2 other
  dimensions: "d194" = 4 distance of point (96, 16.5) L4.end; "d195" = 8 diameter of A2; "d196" = 4 diameter of C1; "d197" = 12 distance between parallel lines of L7 L4; "d198" = 8 diameter of A3; "d199" = 4 diameter of C2; "d200" = 8 diameter of A4; "d201" = 4 diameter of C3; "d202" = 8 diameter of A5; "d203" = 4 diameter of C4; "d204" = 40 distance between parallel lines of L4 L10; "d205" = 12 distance of L1.start point (-25, 16.5); "d206" = 2 distance between parallel lines of L20 L3; "d207" = 2 distance between parallel lines of L18 L2
extrude "돌출24" join sketch "스케치22" stored distance "d208" = 4; taper "d209" = 0 deg
sketch "스케치23"
  geometry: L1 (68, 30)-(68, 5); L2 (0, 30)-(78, 30) reference; L3 (28, 30)-(28, 5); L4 (80, 7.75)-(-65, 7.75) reference; L5 (68, 17.5)-(-65, 17.5); L6 (-65, 30)-(-65, 7) reference; L7 (-53, 40)-(-53, -1); L8 (-8.015, 37)-(-16.015, 37) reference; L9 (-8.015, 37)-(-8.015, 41.3) reference; L10 (-16.015, 41.3)-(-16.015, 37) reference; L11 (-12.015, 41.3)-(-12.015, -1); L12 (-2, -1)-(-59, -1) reference; C1 r 2 at (28, 30) reference; C2 r 2 at (68, 30) reference; C3 r 2 at (68, 5) reference; C4 r 2 at (28, 5) reference; C5 r 2 at (-53, 40) reference; C6 r 2 at (-53, 17.5); C7 r 2 at (28, 17.5); C8 r 2 at (68, 17.5); C9 r 2 at (-12.015, 41.3) reference; C10 r 2 at (-12.015, 17.5); A1 r 4 centre (-12.015, 41.3) between (-8.015, 41.3) and (-16.015, 41.3) reference; 2 further points
  constraints: 10 end point, 7 point on line, 4 centre point, 3 perpendicular, 2 coincident, 2 midpoint, 1 vertical
  dimensions: "d210" = 4 diameter of C6; "d211" = 4 diameter of C7; "d212" = 4 diameter of C8; "d213" = 4 diameter of C10
extrude "돌출25" cut sketch "스케치23" distance "d214" = 34; taper "d216" = 0 deg; dims "d215" = 20, "d217" = 0
sketch "스케치24"
  geometry: C1 r 2 at (28, 17.5) reference; 2 further points
  constraints: 1 coincident
hole "구멍3" sketch "스케치24" at (28, 17.5) diameter "d218" = 4; stored, may be unused: countersink angle "d222" = 90 deg, drill point angle "d224" = 118 deg; dims "d219" = 6, "d220" = 6.2, "d221" = 3, "d223" = 8
sketch "스케치25"
  geometry: C1 r 2 at (68, 17.5) reference; 2 further points
  constraints: 1 coincident
hole "구멍4" sketch "스케치25" at (68, 17.5) diameter "d225" = 4; stored, may be unused: countersink angle "d229" = 90 deg, drill point angle "d231" = 118 deg; dims "d226" = 6, "d227" = 6.2, "d228" = 3, "d230" = 8
sketch "스케치26"
  geometry: C1 r 2 at (-25, -2) reference; C2 r 3.1 at (-25, -2); 1 further point
  constraints: 1 centre point, 1 coincident
  dimensions: "d232" = 6.2 diameter of C2
extrude "돌출26" cut sketch "스케치26" distance "d233" = 34; taper "d235" = 0 deg; dims "d234" = 3, "d236" = 0
sketch "스케치27"
  geometry: L1 (20, -12.5)-(0, -12.5) reference; L2 (20, -12.5)-(20, 11.5) reference; L3 (0, 11.5)-(20, 11.5) reference; L4 (0, 0)-(0, 11.5) reference; L5 (0, -12.5)-(0, 0) reference; C1 r 2 at (9.985, -2) reference; C2 r 3.1 at (9.985, -2); 1 further point
  constraints: 1 centre point, 1 coincident
  dimensions: "d237" = 6.2 diameter of C2
extrude "돌출27" cut sketch "스케치27" distance "d238" = 3; taper "d239" = 0 deg
sketch "스케치28"
  geometry: L1 (-53.47, 16)-(-58, 16) reference; L2 (0, 16)-(-53.47, 16) reference; L3 (0, 16)-(0, 0) reference; L4 (20, 0)-(0, 0) reference; L5 (20, 31)-(20, 0) reference; L6 (20, 31)-(-58, 31) reference; L7 (-58, 16)-(-58, 31) reference; C1 r 2 at (-8, 18.5) reference; C2 r 2 at (-48, 18.5) reference; C3 r 6 at (-48, 18.5); C4 r 6 at (-8, 18.5); 1 further point
  constraints: 2 centre point, 2 coincident
  dimensions: "d240" = 12 diameter of C3; "d241" = 12 diameter of C4
extrude "돌출28" cut sketch "스케치28" extent not by distance; stored distance "d242" = 0; taper "d243" = 0 deg
sketch "스케치29"
  geometry: L1 (-144.725, 76.024)-(196.362, 76.024); L2 (196.362, 76.024)-(196.362, -88.872); L3 (196.362, -88.872)-(-144.725, -88.872); L4 (-144.725, -88.872)-(-144.725, 76.024); 1 further point
  constraints: 8 end point, 2 parallel, 1 horizontal, 1 perpendicular
fillet "모깎기7" dims "d244" = 2
extrude "돌출29" cut sketch "스케치29" extent not by distance; stored distance "d245" = 0; taper "d246" = 0 deg
chamfer "모따기3" distance "d247" = 4; stored, may be unused: second distance "d248" = 2, angle "d249" = 45 deg
sketch "스케치30"
  geometry: C1 r 4.4 at (0, 0) reference; C2 r 5 at (0, 0); 1 further point
  constraints: 1 centre point, 1 coincident
  dimensions: "d250" = 10 diameter of C2
extrude "돌출30" cut sketch "스케치30" extent not by distance; stored distance "d251" = 0; taper "d252" = 0 deg
node "솔리드1"
node "투영된 루프1"
node "투영된 루프2"
node "투영된 루프3"
node "투영된 루프4"
node "투영된 루프5"
node "투영된 루프6"
node "투영된 루프7"
node "투영된 루프8"
node "투영된 루프9"
node "투영된 루프10"
node "투영된 루프11"
node "투영된 루프12"
node "투영된 루프13"
node "투영된 루프14"
node "투영된 루프15"
node "투영된 루프16"
node "투영된 루프19"
node "투영된 루프20"
node "투영된 루프22"
node "투영된 루프23"
node "투영된 루프24"
feature "A9D066F2-1C7D-4E18-AEED-F7BC21143FA4" dims "d88" = 4, "d89" = 6, "d90" = 6.2, "d91" = 4, "d92" = 90 deg, "d93" = 8, "d94" = 0
